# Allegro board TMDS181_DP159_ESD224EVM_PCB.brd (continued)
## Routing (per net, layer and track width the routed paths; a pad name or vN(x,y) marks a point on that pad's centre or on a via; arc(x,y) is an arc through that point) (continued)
X2: length 6
  TOP w0.203: U7.26 27.27,77.83 27.53,78.09 C50.1 27.53,80.72 27.87,81.07 28.56,81.75 Y1.1
N16782838: length 2.2
  TOP w0.203: R77.2 77.2,55.73 R78.2 77.22,56.59 77.22,56.59 U3.1
N16869116: length 4.4
  TOP w0.127: v1(42.72,47.66) 42.59,47.53 42.59,45.65 U1.46
  BOTTOM w0.127: R125.1 v1(42.72,47.66) 42.6,47.54 42.6,47.09 42.21,46.7 41.91,46.7 R129.1
N16869122: length 3.9
  TOP w0.127: v1(42.18,47.66) 42.31,47.53 42.31,45.65 U1.47
  BOTTOM w0.127: R126.1 v1(42.18,47.66) ; v1(42.18,47.66) 42.18,47.66 ; v1(42.18,47.66) 42.32,47.52 42.32,47.21 42.1,46.98 41.9,46.98 41.78,47.11 R130.1
N16874758: length 2.2
  BOTTOM w0.203: R66.2 59.85,29.53 59.86,29.52 J7.1
N16874763: length 2.1
  BOTTOM w0.203: R69.1 59.99,24.43 60,24.44 J7.3
N16880319: length 24.7
  TOP w0.127: v1(22.21,46.99) 22.29,46.91 R14.2
  BOTTOM w0.127: P1.1 11.93,56.57 12.29,56.21 20.88,56.21 22.85,54.24 22.85,49.24 21.12,47.5 21.12,46.28 21.33,46.06 21.97,46.06 22.21,46.3 v1(22.21,46.99)
N16880326: length 24.7
  TOP w0.127: v1(22.21,44.86) 22.29,44.93 R15.2
  BOTTOM w0.127: P1.3 11.93,55.57 12.29,55.93 20.76,55.93 22.57,54.13 22.57,49.35 20.84,47.62 20.84,46.17 21.22,45.78 21.97,45.78 22.21,45.54 v1(22.21,44.86)
N16880333: length 24.7
  TOP w0.127: v1(22.21,43.97) 22.29,43.89 R18.2
  BOTTOM w0.127: P1.4 11.93,55.07 12.29,54.71 13.32,54.71 13.76,55.15 18.88,55.15 20.14,53.89 20.14,43.47 20.57,43.04 21.97,43.04 22.21,43.28 v1(22.21,43.97)
N16880340: length 24.7
  TOP w0.127: v1(22.21,41.83) 22.29,41.91 R19.2
  BOTTOM w0.127: v1(22.21,41.83) 22.21,42.52 21.97,42.76 20.46,42.76 19.86,43.36 19.86,53.78 18.76,54.87 13.88,54.87 13.43,54.43 12.29,54.43 11.93,54.07 P1.6
N16880347: length 24.7
  TOP w0.127: v1(22.19,40.92) 22.26,40.84 R20.2
  BOTTOM w0.127: v1(22.19,40.92) 22.19,40.23 21.95,39.99 20.44,39.99 19.1,41.34 19.1,51.36 17.25,53.21 12.29,53.21 11.93,53.57 P1.7
N16880354: length 24.7
  TOP w0.127: v1(22.19,38.79) 22.26,38.86 R21.2
  BOTTOM w0.127: v1(22.19,38.79) 22.19,39.47 21.95,39.71 20.33,39.71 18.82,41.22 18.82,51.24 17.13,52.93 12.29,52.93 11.93,52.57 P1.9
N16880361: length 24.7
  TOP w0.127: v1(22.25,37.87) 22.33,37.8 R22.2
  BOTTOM w0.127: P1.10 11.93,52.07 12.29,51.71 15.52,51.71 18,49.23 18,40.42 21.48,36.94 22.01,36.94 22.25,37.19 v1(22.25,37.87)
N16880368: length 24.7
  TOP w0.127: v1(22.25,35.74) 22.33,35.81 R23.2
  BOTTOM w0.127: v1(22.25,35.74) 22.25,36.42 22.01,36.66 21.37,36.66 17.72,40.31 17.72,49.11 15.41,51.43 12.29,51.43 11.93,51.07 P1.12
N16881139: length 7.8
  TOP w0.203: J6.3 25.46,11.71 J5.3
N16881148: length 9
  BOTTOM w0.203: J5.1 32.48,10.82 J4.3
N16883754: length 2.2
  BOTTOM w0.203: R75.2 67.06,22 67.07,22 J8.1
N16883759: length 12.1
  TOP w0.203: R76.2 R76.1 65.17,15.03 65.5,15.36 R115.1 67.23,15.36 J8.3
N16887406: length 1.5
  TOP w0.203: R102.2 24.84,67.25 24.87,67.28 U7.12
N16887471: length 2.6
  TOP w0.203: R96.2 17.4,77.48 17.4,79.6 J13.3
N16892757: length 5.9
  BOTTOM w0.203: R5.2 14.41,19.56 R12.2 10.8,19.54 9.93,20.42 Q1.1
N16892765: length 3.7
  BOTTOM w0.203: Q2.1 10.08,16.84 9.22,17.7 R11.1 9.7,18.1 10.05,18.45 Q1.3
N16892877: length 2.7
  BOTTOM w0.203: Q2.3 10.97,13.92 11.6,13.29 R13.1
N16906083: length 3.1
  TOP w0.203: C7.1 v1(29.38,30.86)
  BOTTOM w0.203: v1(29.38,30.86) C5.2 28.46,30.84 R36.2
N16910161: length 3.4
  TOP w0.203: v1(22.23,30.89) 23.27,30.89 C6.2
  BOTTOM w0.203: v1(22.23,30.89) C4.2 23.28,30.12 23.27,30.11 R35.2
N16913511: length 2.6
  TOP w0.203: J13.2 17.05,79.6 17.05,77.48 R95.2
N16916452: length 7.8
  TOP w0.203: R122.1 26.03,63.25 JP1.1 24.56,64.21 24.07,64.7 U7.11
N16916458: length 7.1
  TOP w0.203: U8.6 21.81,60.68 21.82,60.67 R100.2 23.56,60.67 23.6,60.71 JP1.2 26.14,60.71 R122.2
N16916991: length 14.6
  TOP w0.203: U7.10 23.27,67.27 23.29,67.25 R99.2 21.7,66.76 20.78,65.84 18.69,65.84 18.21,65.35 18.21,59.93 18.73,59.41 U8.5
N16919313: length 2.6
  TOP w0.203: U7.5 v1(20.1,71.96)
  BOTTOM w0.203: v1(20.1,71.96) 21,71.96 21.11,72.07 R94.1
N16919318: length 11.4
  TOP w0.203: v1(22.14,71.16) U7.6 20.93,70.94 18.33,70.94 17.4,71.87 17.4,76.44 R96.1
  BOTTOM w0.203: C45.1 22.66,71.16 v1(22.14,71.16) 21.72,71.16 R94.2
N16919400: length 11.3
  TOP w0.203: R95.1 17.05,76.44 17.05,71.72 18.19,70.59 20.93,70.59 U7.7 v1(22.15,70.36)
  BOTTOM w0.203: v1(22.15,70.36) 22.65,70.36 C49.2
N16919998: length 1.5
  TOP w0.203: U7.1 20.21,75.16 20.19,75.15 R101.1
N16925972: length 17.5
  TOP w0.127: U1.2 40.71,44.05 37.58,44.05 35.55,46.08 30.79,46.08 30.57,46.3 28.75,46.3 28.53,46.08 24.7,46.08 C11.2
N16925975: length 17.5
  TOP w0.127: U1.3 40.71,43.77 37.46,43.77 35.43,45.8 30.68,45.8 30.45,46.03 28.87,46.03 28.65,45.8 24.7,45.8 C12.2
N16925996: length 17.5
  TOP w0.127: U1.12 40.71,39.27 39.62,39.27 35.32,39.27 32.7,36.65 24.74,36.65 C25.2
N16925999: length 17.5
  TOP w0.127: U1.11 40.71,39.55 39.74,39.55 35.2,39.55 32.59,36.93 24.76,36.93 C24.2
N16926002: length 17.5
  TOP w0.127: C16.2 24.7,39.71 26.29,39.71 27.03,40.45 28.81,40.45 29.51,39.74 32.79,39.74 33.82,40.77 40.71,40.77 U1.9
N16926005: length 17.5
  TOP w0.127: U1.8 40.71,41.05 33.7,41.05 32.67,40.02 29.63,40.02 28.93,40.72 26.91,40.72 26.17,39.99 24.7,39.99 C15.2
N16926008: length 17.5
  TOP w0.127: C14.2 24.7,42.75 28.33,42.75 29.31,43.74 30.4,43.74 31.39,42.75 36,42.75 36.48,42.27 40.71,42.27 U1.6
N16926011: length 17.5
  TOP w0.127: U1.5 40.71,42.55 36.6,42.55 36.11,43.03 31.5,43.03 30.52,44.02 29.2,44.02 28.21,43.03 24.7,43.03 C13.2
N16928798: length 2.1
  TOP w0.203: J2.18 v1(12.12,33.96)
  BOTTOM w0.203: v1(12.12,33.96) 11.48,33.96 R33.2
N16928867: length 1.4
  TOP w0.203: C7.2 26.91,30.71 R34.2
N16961958: length 3.4
  TOP w0.203: U9.4 70.59,37.04 71.23,37.68 U2.1
N16965307: length 2
  TOP w0.203: R83.1 R120.1 49.96,74.59 49.98,74.6 U4.7
N16965335: length 1.4
  TOP w0.203: U4.9 51.14,73.38 C34.1
N16968702: length 2.4
  TOP w0.203: R98.2 30.49,74.37 30.49,74.36 U7.23 U7.24
N16982334: length 2.1
  TOP w0.203: U8.7 21.6,61.95 21.62,61.96 R121.1
N17009590: length 5.4
  TOP w0.203: R123.1 J18.1
N17009600: length 25.9
  TOP w0.127: U1.35 48.18,44.05 66.08,44.05 66.1,44.07 69.87,44.07 ; 69.87,44.07 72.25,44.07 72.26,44.08 73.73,44.08 U10.6 ; 69.87,44.07 R123.2
N17009604: length 26
  TOP w0.127: U1.34 48.19,43.77 66.2,43.77 66.22,43.79 69.87,43.79 ; R124.2 69.87,43.79 ; 69.87,43.79 72.28,43.79 72.28,43.8 73.7,43.8 U10.7
N17009633: length 25.9
  TOP w0.127: U11.7 73.7,40.76 72.15,40.76 72.14,40.77 48.19,40.77 U1.28
N17009635: length 25.8
  TOP w0.127: U11.6 73.73,41.04 72.27,41.04 72.25,41.05 48.19,41.05 U1.29
N17009637: length 25.8
  TOP w0.127: U1.31 48.19,42.27 72.26,42.27 72.27,42.28 73.73,42.28 U10.10
N17009639: length 25.9
  TOP w0.127: U1.32 48.19,42.55 72.15,42.55 72.16,42.56 73.71,42.56 U10.9
N17009643: length 25.9
  TOP w0.127: U1.26 48.19,39.54 72.24,39.54 72.27,39.52 73.72,39.52 U11.9
N17009645: length 25.8
  TOP w0.127: U1.25 48.18,39.26 72.13,39.26 72.15,39.24 73.72,39.24 U11.10
N170364390: length 1.2
  TOP w0.381: D2.1 38.16,73.56 38.15,73.57 R82.1

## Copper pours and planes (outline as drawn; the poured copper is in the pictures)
GND on L2, L5: 0.51,0.51 88.44,0.51 88.44,83.36 0.51,83.36
VCC_3P3V on TOP: 51.26,79.44 51.26,82.13 50.3,83.09 47.44,83.09 47.08,82.74 47.08,80.45 48.74,80.45 49.76,79.44
VCC_3P3V on L4: 35.51,5.74 30.34,10.91 22.68,10.91 20.05,13.54 20.05,16.96 22.28,19.2 22.28,29.11 20.05,31.35 20.05,44.38 41.49,65.82 41.49,83.36 88.44,83.36 88.44,50.52 73.58,50.52 70.7,47.64 70.7,33.53 77.41,26.81 77.41,15.26 67.9,5.74 ; 1 cut-out
VDD_1P1V on TOP: 42.73,71.5 44.33,71.5 45.18,70.65 45.18,67.72 44.55,67.09 41.65,67.09 41.07,67.67 41.07,69.41 42.69,71.03 42.69,71.46
VDD_1P1V on L3: 38.72,36.36 38.72,73.05 44.79,73.05 44.79,52.78 50.2,47.37 50.2,36.36
BOARD_1P1V on TOP: 41.53,75.9 41.53,75.03 40.92,75.03 40.92,73.43 40.94,73.41 42.7,73.41 42.72,73.38 42.72,71.96 44.25,71.96 44.37,72.09 44.37,73.61 44.27,73.71 43.71,73.71 43.61,73.81 43.61,75.64 43.54,75.72 42.32,75.72 42.14,75.9
BOARD_3P3V on TOP: 54.94,83.08 54.94,79.2 51.77,79.2 51.77,83.08
BOARD_3P3V on L3: 0.51,0.51 0.51,83.36 88.44,83.36 88.44,0.51 ; 2 cut-outs
BOARD_5V on TOP: 37.26,76.09 37.26,74.49 37.08,74.31 37.08,72.74 35.76,72.74 35.71,72.79 35.71,74.76 36.28,75.34 36.28,76.08 36.29,76.09
BOARD_5V on L4: 0.51,0.51 0.51,83.36 40.47,83.36 40.47,66.24 19.03,44.8 19.03,31.01 19.6,31.01 21.31,29.31 21.31,19.18 19.03,16.9 19.03,13.12 22.26,9.89 29.92,9.89 35.09,4.73 68.32,4.73 78.43,14.84 78.43,27.23 71.71,33.95 71.71,47.22 74,49.51 88.44,49.51 88.44,0.51
BOARD_IN on TOP: 54.53,69.09 53.64,69.98 51.23,69.98 51.23,71.55 51.89,72.21 51.89,73.81 53.31,73.81 53.31,74.24 53.34,74.27 54.28,74.27 54.28,73.1 54.89,72.49 62.13,72.49 62.97,71.65 62.97,69.85 62.2,69.09 ; 1 cut-out
FB_1PT2V on TOP: 40.56,76.96 40.56,76.43 40.61,76.38 42.04,76.38 42.29,76.63 43.61,76.63 43.61,77.04 40.64,77.04
PWRIN_SW on TOP: 60.02,63.78 59.54,64.26 59.54,67.94 66.93,67.94 71.78,72.8 74.47,72.8 75.46,71.81 75.46,66.98 72.26,63.78 ; 2 cut-outs
REG_PG on TOP: 47.37,76 49.78,76 49.78,77.01 49.81,77.04 51.41,77.04 51.41,75.9 51.66,75.9 51.69,75.92 51.69,77.57 51.64,77.62 49.08,77.62 49.05,77.59 49.06,77.59 49.06,76.87 48.56,76.38 47.4,76.38 47.37,76.35
REG_PG on L4: 54.39,78.72 48,78.72 46.95,77.67 46.95,75.21 61.31,60.85 78.02,60.85 79,61.83 79,63.55 76.62,65.94 69.14,65.94 69.1,65.91 67.21,65.91
USB_5V on TOP: 16.05,80.98 16.05,78.26 15.6,77.82 14.53,77.82 14.53,74.92 14.83,74.62 15.88,74.62 16.09,74.83 16.09,77.58 16.48,77.97 16.48,80.99 16.05,80.99
USB_5V on BOTTOM: 14.01,74.98 14.64,74.35 15.69,74.35 18.57,77.23 21.83,77.23 23.77,79.16 53.89,79.16 59.89,73.16 62.91,73.16 64.91,75.16 64.91,79.41 61.26,83.06 23.64,83.06 21.88,81.3 15.22,81.3 14.01,80.08 ; 1 cut-out
N16962991 on TOP: 35.36,80.09 35.36,78.66 35.65,78.37 36.1,78.37 36.23,78.23 36.23,77.47 36.27,77.43 36.68,77.43 36.69,77.44 36.69,78.22 36.93,78.46 37.49,78.46 37.62,78.59 37.62,80.09 37.62,80.1 35.36,80.1
N16965311 on TOP: 51.89,75.9 53.21,75.9 53.24,75.92 53.24,76.89 53.62,77.27 54.94,77.27 54.99,77.32 54.99,78.61 54.91,78.69 52.86,78.69 52.76,78.59 52.76,77.19 52.35,76.78 51.89,76.78

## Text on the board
BOTTOM: LAYER 6 - BOTTOM
Board Geometry/Soldermask Bottom: LAYER 8 - SOLDERMASK BOTTOM
Package Geometry/Pastemask Bottom: LAYER 10 - SOLDERPASTE BOTTOM
Ref Des/Silkscreen Bottom: FOR EVALUATION ONLY: | NOT FCC APPROVED FOR RESALE | LAYER 12 - SILKSCREEN BOTTOM
TOP: LAYER 1 - TOP
Board Geometry/Soldermask Top: LAYER 7 - SOLDERMASK TOP
Package Geometry/Pastemask Top: LAYER 9 - SOLDERPASTE TOP
Ref Des/Silkscreen Top: JP 2-3 FOR TMDS181 | JP 1-2 FOR DP159 THRU HDMI | NC FOR DP159 | SRCN | OUT | ARC | AUX | SRCP | SPDIF | IN | J1 | SDA_USB | SDA_AAR | SDA | SCL_USB | SCL_AAR | SCL | GND | VDD_1P1V | SIG_EN | LO | HI | VCC_3P3V | I2C_EN | PIN | /POL | SWAP | EQ_SEL | A0 | PRE_SEL | SLEW_CTL | /TEST/A1 | HDMI_SEL | VSADJ | POT | DEFAULT | BOARD_RESET | TX_TERM_CTL | J16 | USB 5V | WALL | OFF | TMDS181_DP159_ESD224EVM_REVA | LAYER 11 - SILKSCREEN TOP
L2: LAYER 2 - GND
L3: LAYER 3 - PWR
L4: LAYER 4 - PWR
L5: LAYER 5 - GND
PAGE_OUTLINE: 20mil | 5mil | 1 | 2 | 3 | 4 | 5 | 6 | TOP | LAYER2 GND | LAYER3 PWR | LAYER4 PWR | LAYER5 GND | BOTTOM | 9 | 10 | 4.ALL BOARDS MUST MEET OT EXCEEED UL94-V0 REQUIRMENTS. | PCB MUST BEAR THE UL094-0-UL REGISTERD MATERIAL ID NUMBER | GENERAL NOTES. UNLESS OTHERWISE SPECIFIED | 1.  ALL FABRICATION ITEMS MUST MEET OR EXCEED BEST | INDUSTRY PRACTICE : IPC-A-600C (Commercial std.) | 2.  LAMINATE MATERIAL  :  FR4 POLYCLAD 370 or EQUIVALENT | 3.  COPPER WEIGHT  : 1oz START INTERNAL, 1/2oz START EXTERNAL | 4.  FINISHED BOARD THICKNESS :  .062"  +/- 10% | 5.  MAXIMUM WARP AND TWIST TO BE :  .005 INCH PER INCH | 6.  MINIMUM COPPER WALL THICKNESS OF PLATED-THRU | HOLES TO BE .001 INCH. THERE MUST BE 1MIL OR GREATER PLATING ON | EACH SIDE OF THE BARREL WHEN VIEWED IN THE CROSS SECTION | 7.  MINIMUM ANNULAR RING OF PLATED-THRU HOLES | TO BE .002 INCH | 8.  MAXIMUM ALLOWABLE LINE REDUCTION TO BE | 20% OR .002" WHICHEVER IS SMALLER | 9.  0.005" SIGNAL LINES WITH 0.006" SPACING ON LAYER 1 & 6 TO BE | IMPEDANCE CONTROLLED 100 OHMS DIFFERENTIAL +/- 5% | 10. 0.008" SIGNAL LINES ON LAYER 1 & 6 TO BE | IMPEDANCE CONTROLLED 50 OHMS +/- 5% | 11. DIELECTRIC CONSTANTS ARE         CORE : 4.1 | PREPREG : 4.1 | 12. SOLDERMASK CLEARANCE IS GIVEN AS SAME AS PAD SIZE FOR ALL SMT COMPONENT. | VENDOR SHALL OVERSIZE THE MASK CLEARANCES AS PER THEIR MANUFACTURE CAPABILITIES. | 13. 0.008" AND 0.012"  DRILL VIAS NEED TO BE TENTED FROM BOTH SIDE. | PROCESS NOTES | 1. CIRCUITRY ON OUTER LAYERS TO BE PLATED WITH : ENIG | 2. SOLDERMASK BOTH SIDES PER ARTWORK  :  GREEN LPI | 3. SILKSCREEN BOTH SIDES PER ARTWORK  :  COLOR = WHITE | LAYER 13 - FAB | ALL DIMENSIONS ARE IN INCHES | 2 PLACES | R 0.0167
PLACE_BOUND_BOTTOM: ASSEMBLY TOP
User.6: ASSEMBLY BOTTOM
User.11: FIGURE | SIZE | 160.0 | 140.0 | 120.0 | 98.0 | 90.55 | 73.0 | 62.99 | 59.06 | 52.0 | 40.0 | 39.0 | 38.0 | 12.0 | 8.0 | 55.12 | 41.34 | 106.3x35.43 | 66.93x35.43 | 62.99x23.62 | 51.18x23.62 | 43.31x23.62 | 33.46x25.59 | DRILL CHART: TOP to BOTTOM | ALL UNITS ARE IN MILS | TOLERANCE | +3.0/-3.0 | +2.99/-2.99 | +0.0/-12.0 | +0.0/-8.0 | +1.97/-1.97 | +1.0/-1.0 | +3.15/-3.15 | PLATED | NON-PLATED | QTY | 4 | 1 | 2 | 3 | 9 | 10 | 41 | 12 | 302
